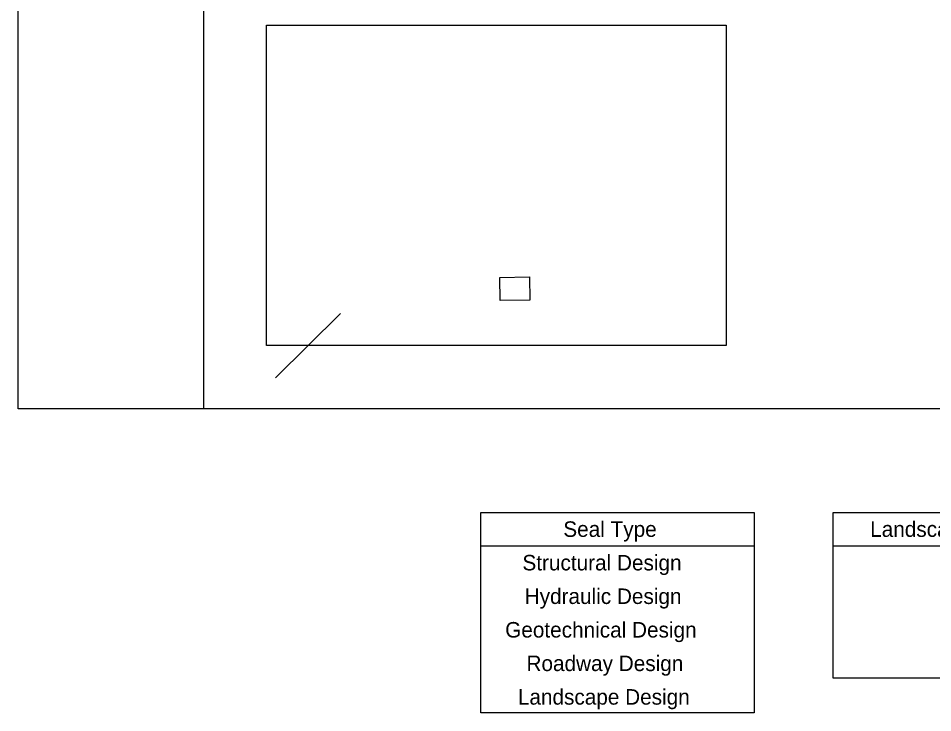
# Model space of a CAD drawing. Extents: x -0.84 to 4.97, y -1.01 to 2.42.
# Drawn here: x 0.11 to 0.723, y -0.1 to 0.365 of the extents above; entities that cross this region are included whole.
import ezdxf

# ---------------------------------------------------------------- set-up
doc = ezdxf.new("R2010")
doc.units = 0
for name, color, linetype in [('OBD_Construction_Line', 7, 'Continuous'), ('SheetBorder', 7, 'Continuous'), ('SheetGridMinor', 7, 'Continuous'), ('SheetText', 7, 'Continuous'), ('tdCoTitleBlock', 7, 'Continuous'), ('TextNonPlot', 7, 'Continuous')]:
    doc.layers.add(name, color=color, linetype=linetype)

msp = doc.modelspace()

# ---------------------------------------------------------------- linework, layer by layer
at = {"layer": 'OBD_Construction_Line'}
msp.add_lwpolyline([(0.11042, 1.78667), (2.72292, 1.78667), (2.72292, 0.10333), (0.11042, 0.10333)], close=True, dxfattribs=at)
at = {"layer": 'SheetBorder'}
msp.add_line((0.23451, 1.78667), (0.23451, 0.10333), dxfattribs=at)
at = {"layer": 'SheetGridMinor'}
for p, q in [((0.42043, 0.01144), (0.60365, 0.01144)), ((0.65659, 0.01144), (0.8398, 0.01144))]:
    msp.add_line(p, q, dxfattribs=at)
at = {"layer": 'SheetText'}
for points in [[(0.42043, 0.03394), (0.60365, 0.03394), (0.60365, -0.10042), (0.42043, -0.10042)], [(0.65659, 0.03394), (0.8398, 0.03394), (0.8398, -0.0772), (0.65659, -0.0772)]]:
    msp.add_lwpolyline(points, close=True, dxfattribs=at)
at = {"layer": 'tdCoTitleBlock'}
msp.add_lwpolyline([(0.43322, 0.19134), (0.45301, 0.19177), (0.4533, 0.17631), (0.43336, 0.176)], close=True, dxfattribs=at)
at = {"layer": 'TextNonPlot'}
msp.add_line((0.32647, 0.16724), (0.28273, 0.12407), dxfattribs=at)
msp.add_lwpolyline([(0.27688, 0.36067), (0.58484, 0.36067), (0.58484, 0.14591), (0.27688, 0.14591)], close=True, dxfattribs=at)

# ---------------------------------------------------------------- texts
at = {"layer": 'SheetText'}
for s, p in [('Seal Type', (0.47575, 0.01749)), ('Landscape Design', (0.68144, 0.01749)), ('Structural Design', (0.44835, -0.00501)), ('Hydraulic Design', (0.44986, -0.02751)), ('Geotechnical Design', (0.43678, -0.05001)), ('Roadway Design', (0.45106, -0.07251)), ('Landscape Design', (0.44529, -0.09501))]:
    msp.add_text(s, height=0.0104, dxfattribs=at).set_placement(p)

doc.saveas('drawing.dxf')
